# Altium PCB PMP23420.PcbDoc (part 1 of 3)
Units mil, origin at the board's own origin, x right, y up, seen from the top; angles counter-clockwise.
Board outline 5200 x 3400 mil, 6 copper layers (Top Layer, Midlayer 1, Midlayer 2, Midlayer 3, Midlayer 4, Bottom Layer), stack 61.536 mil thick; 227 components, 56 nets, 480 pads, 964 vias.
Unrouted connection lines stored in the file: 22.
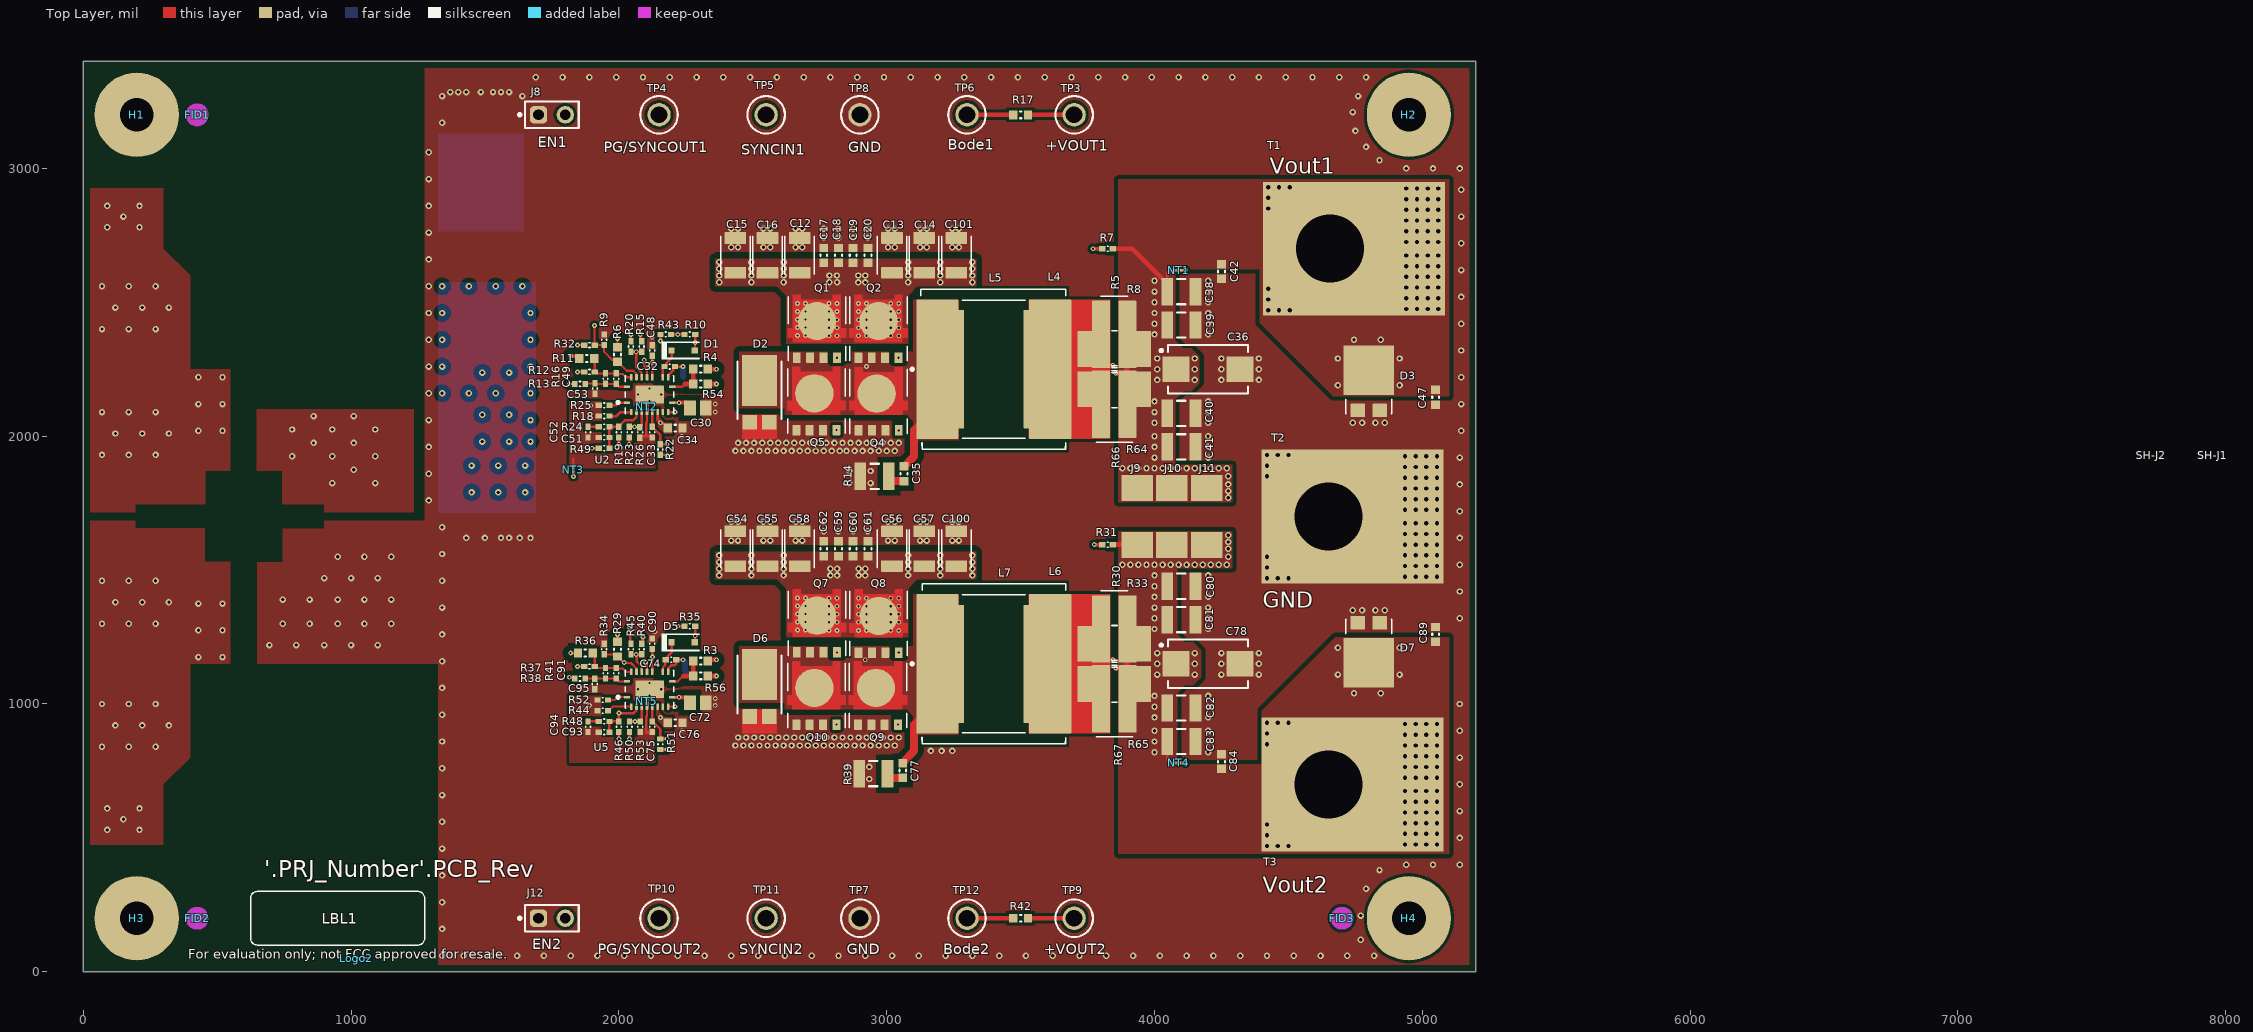
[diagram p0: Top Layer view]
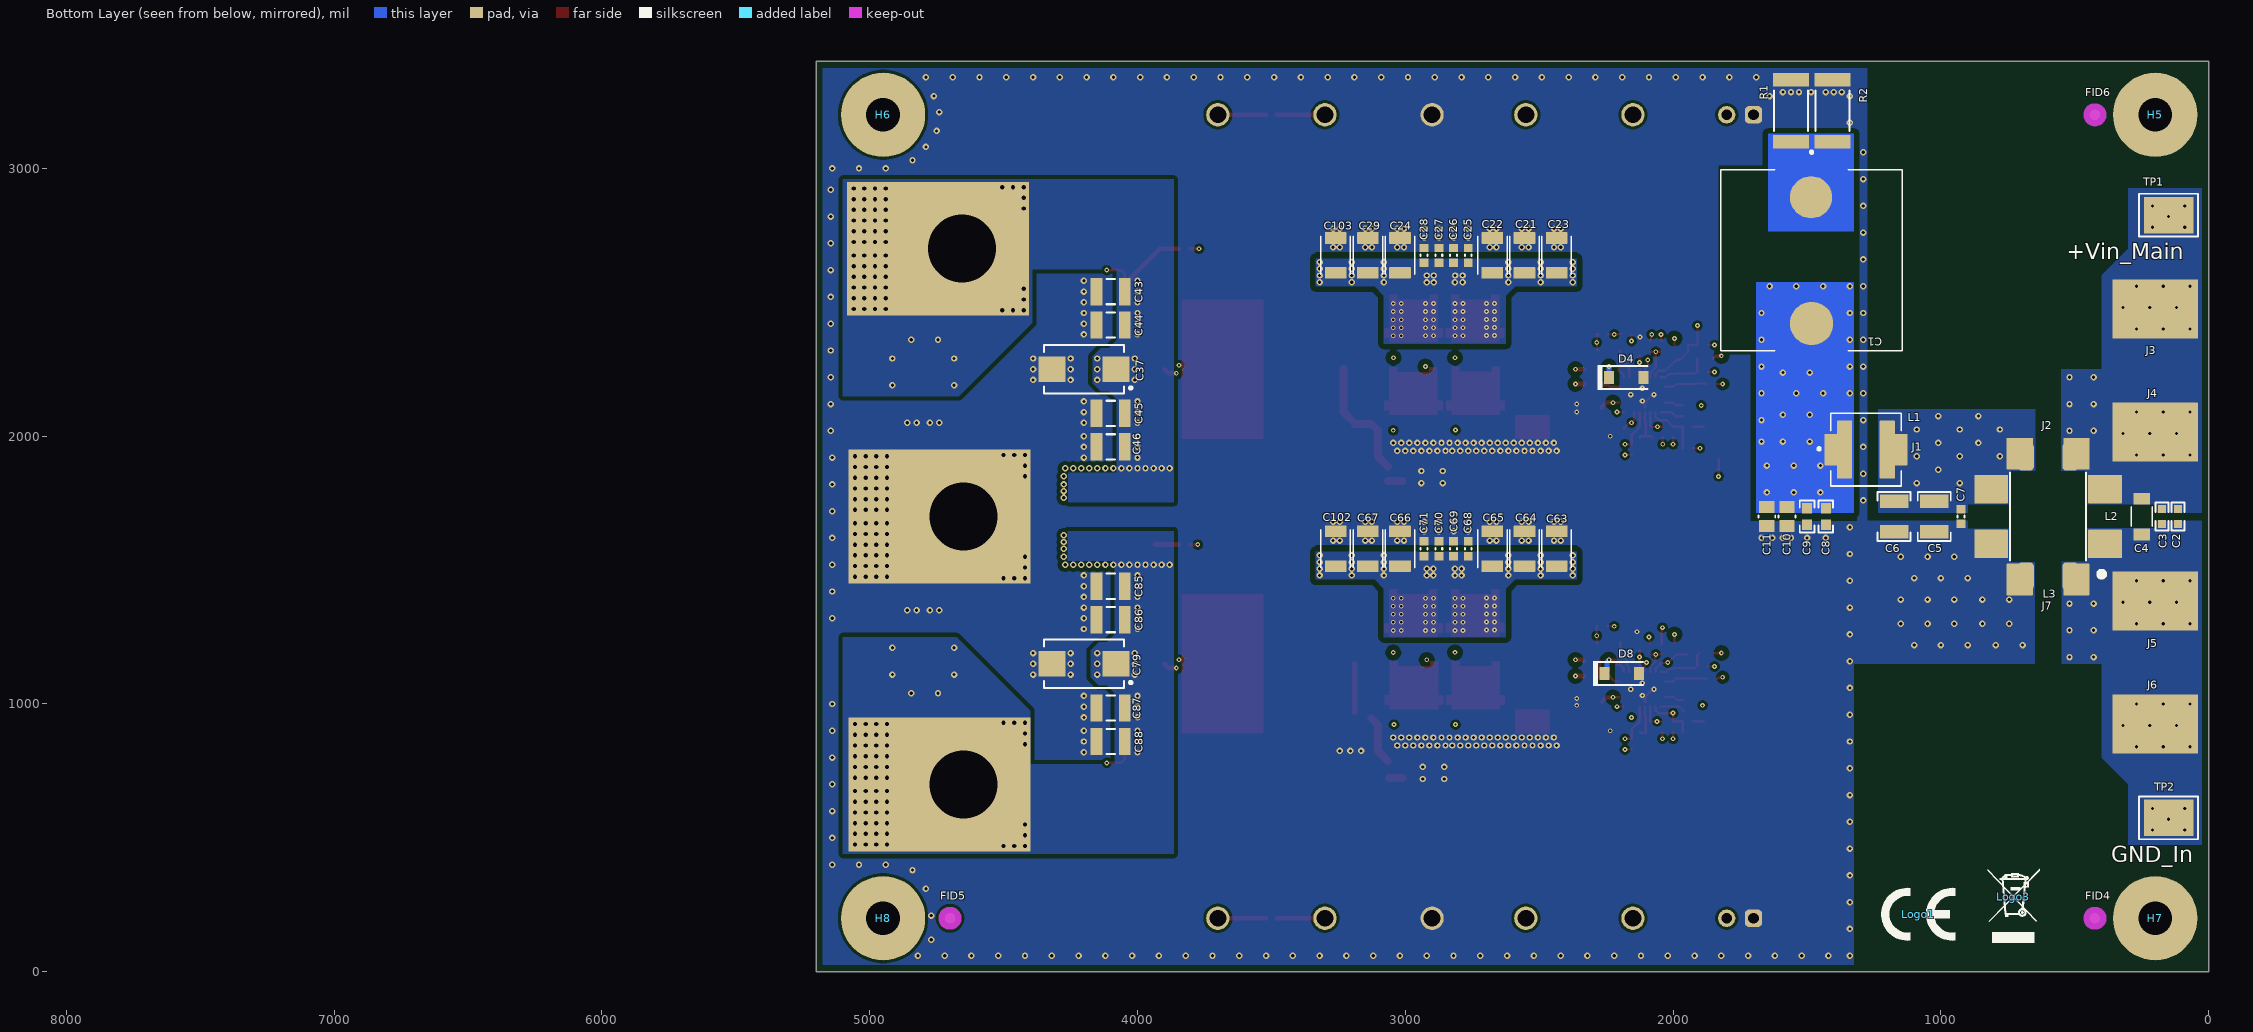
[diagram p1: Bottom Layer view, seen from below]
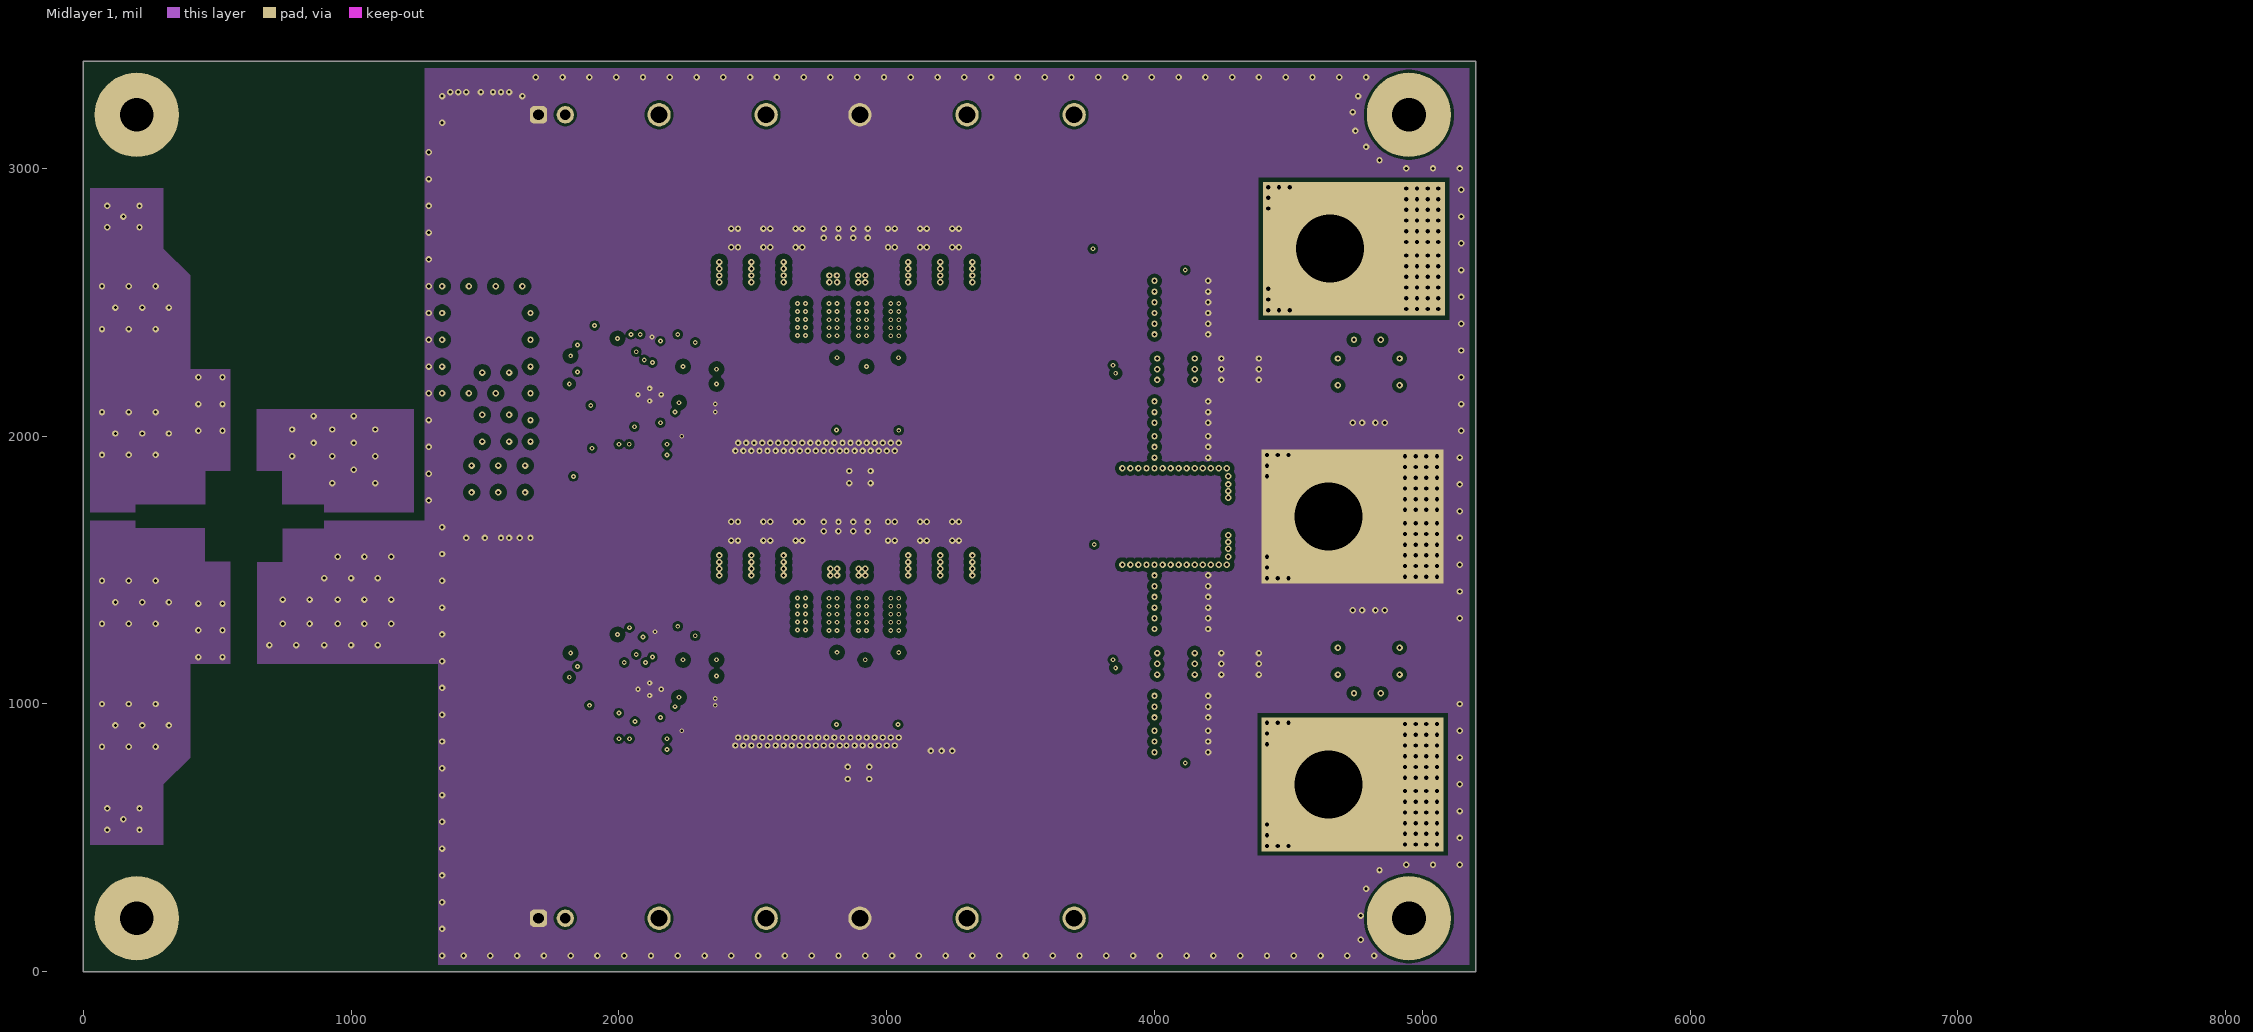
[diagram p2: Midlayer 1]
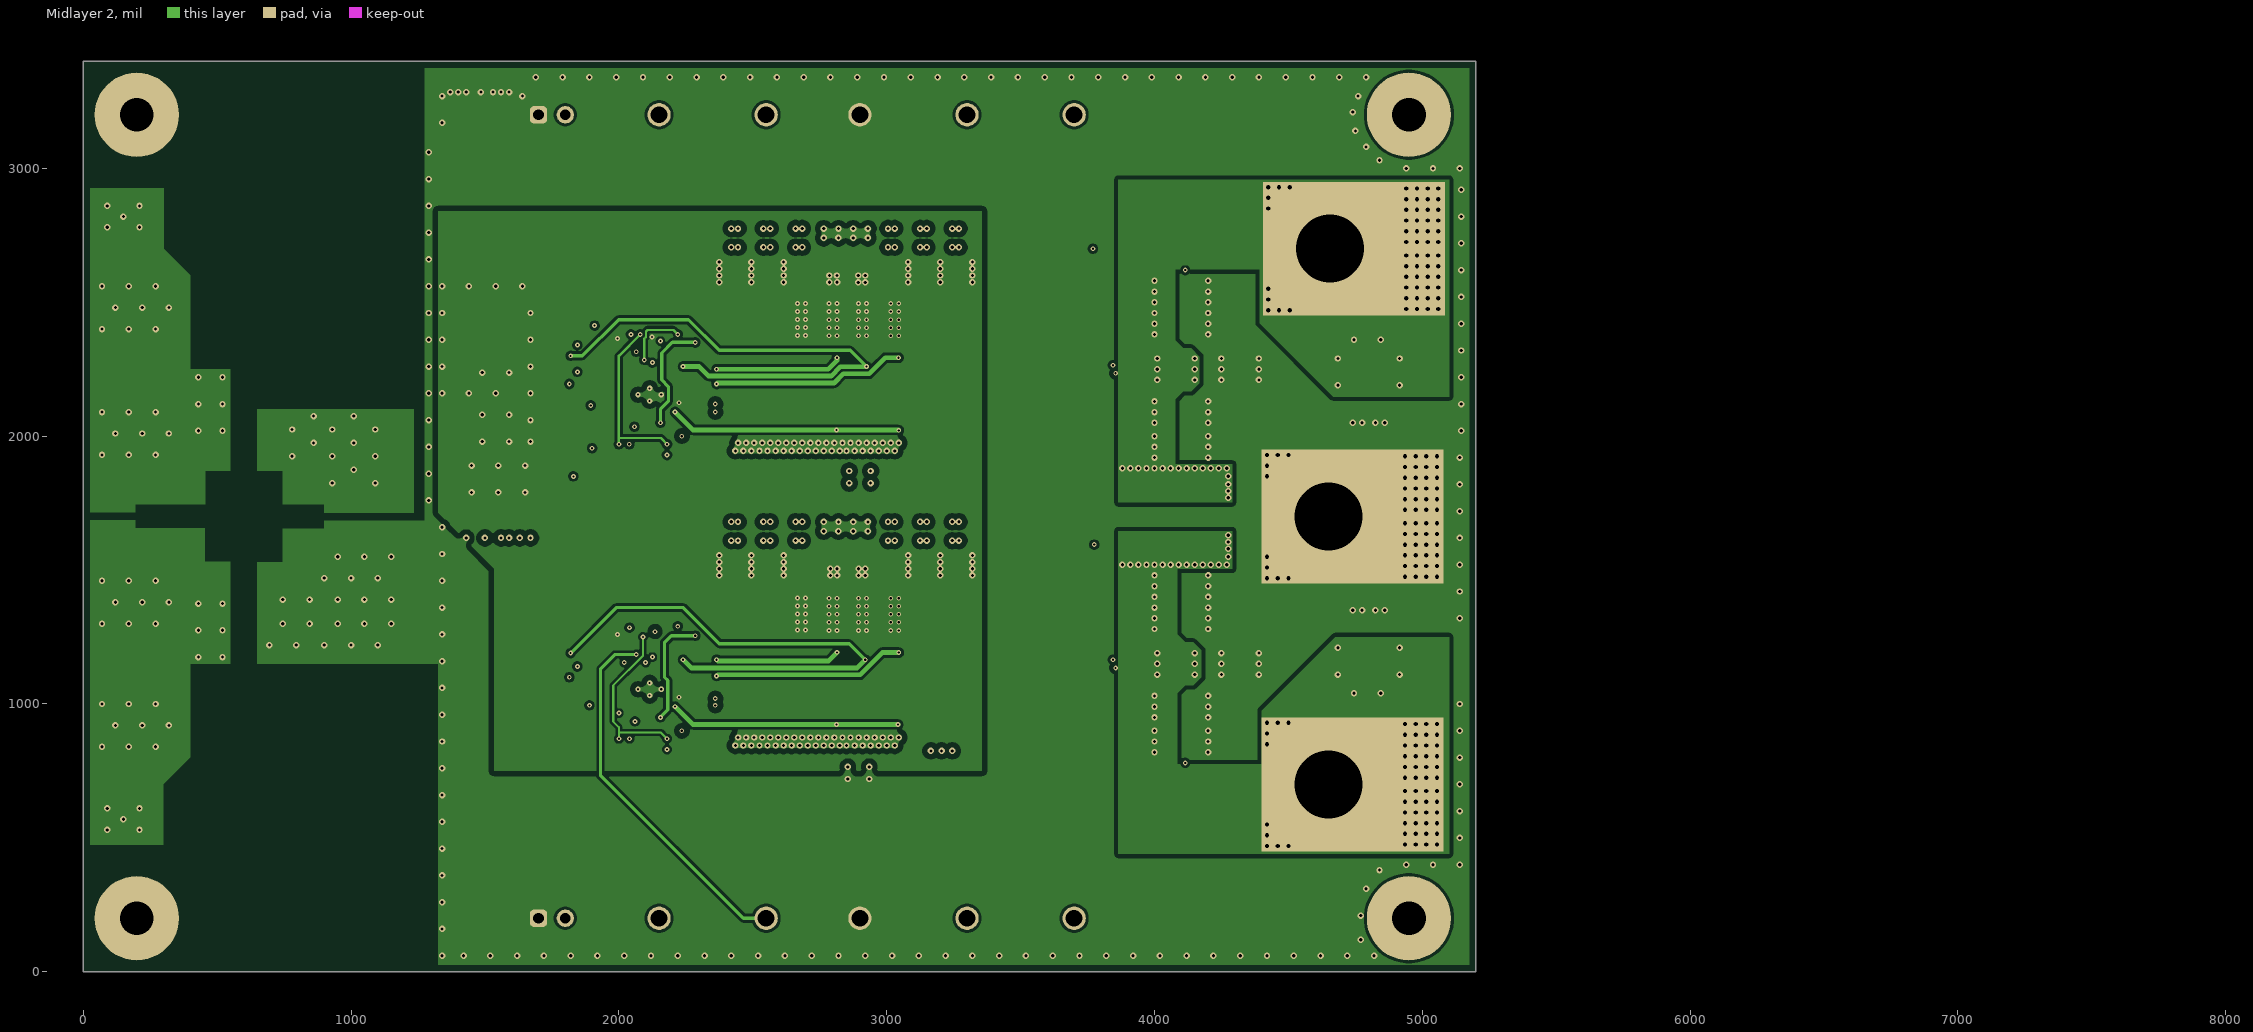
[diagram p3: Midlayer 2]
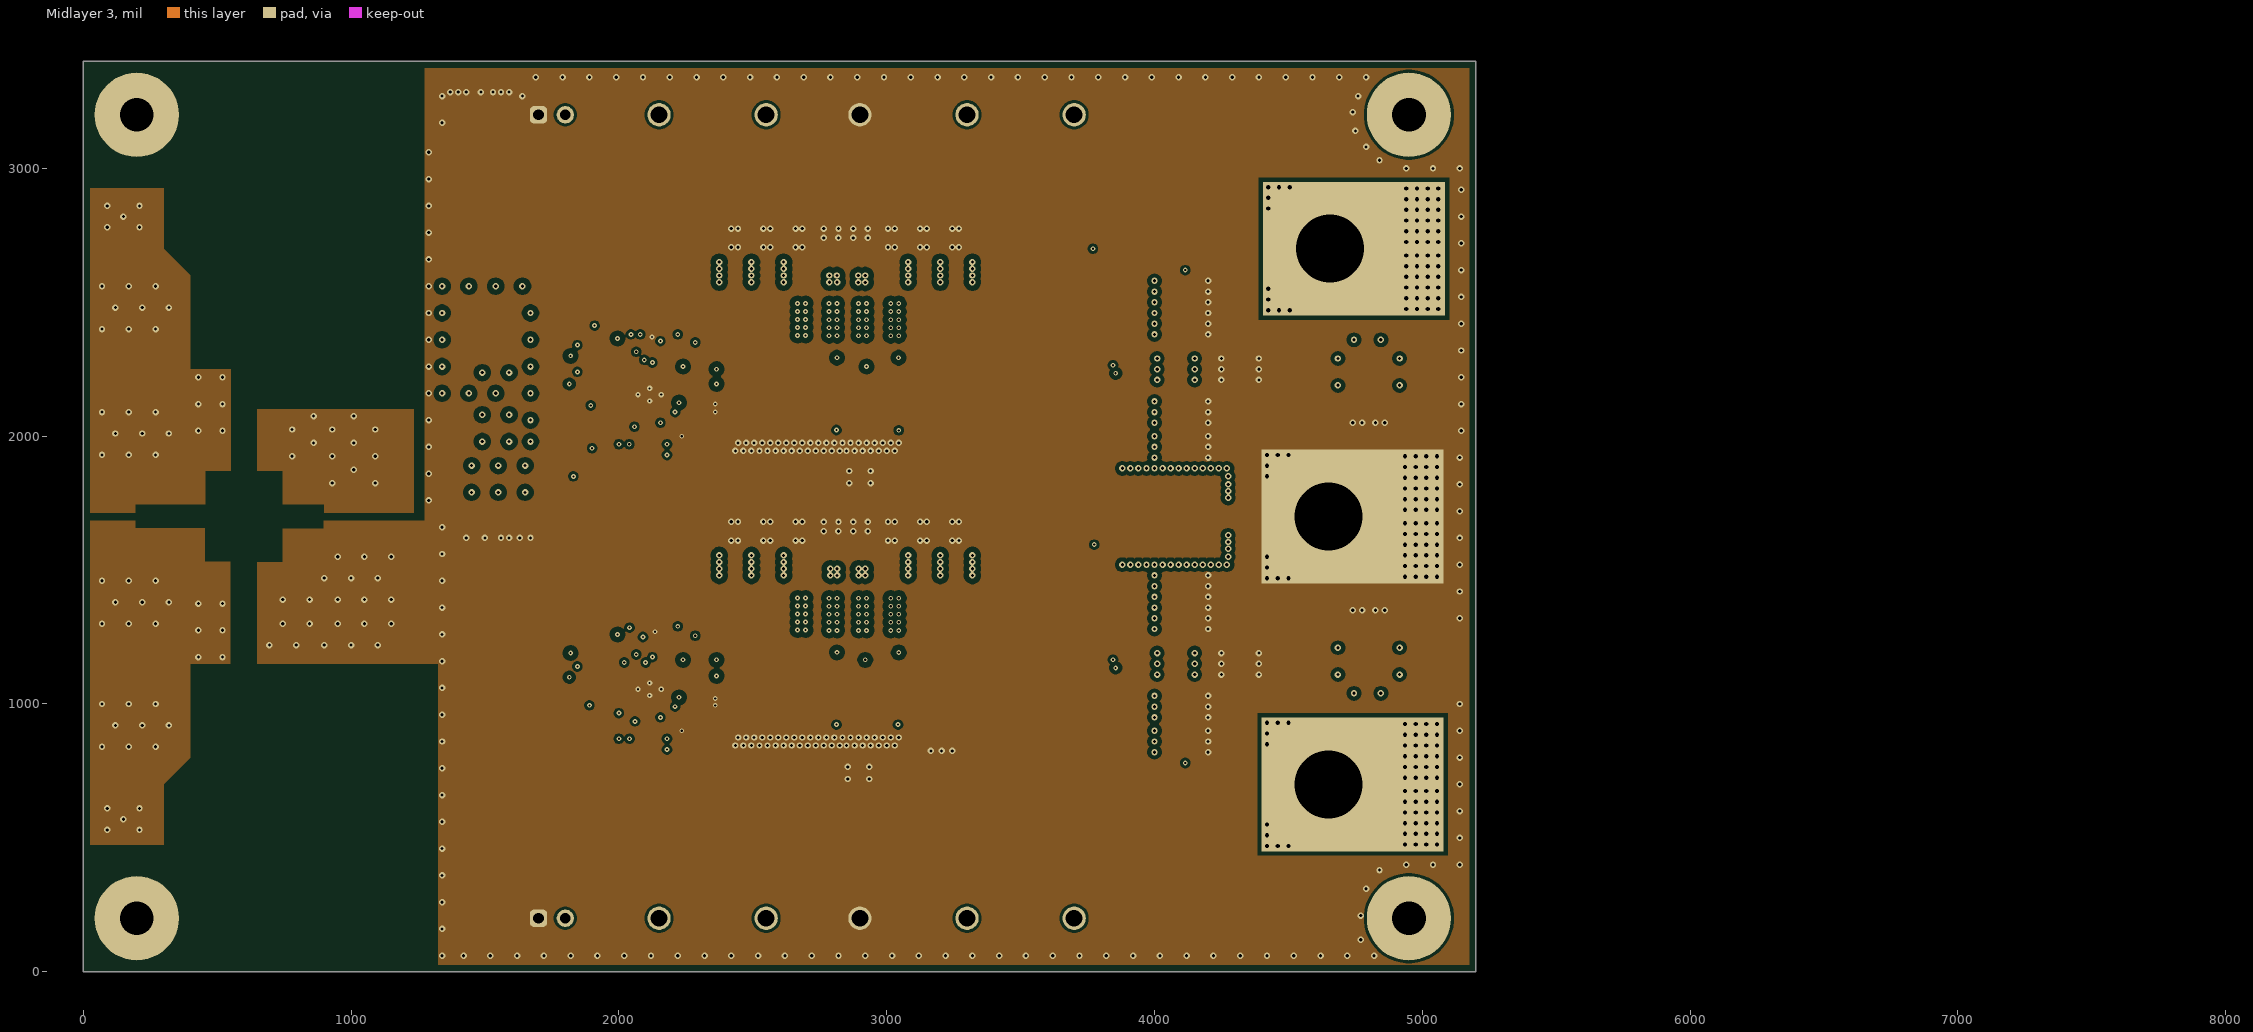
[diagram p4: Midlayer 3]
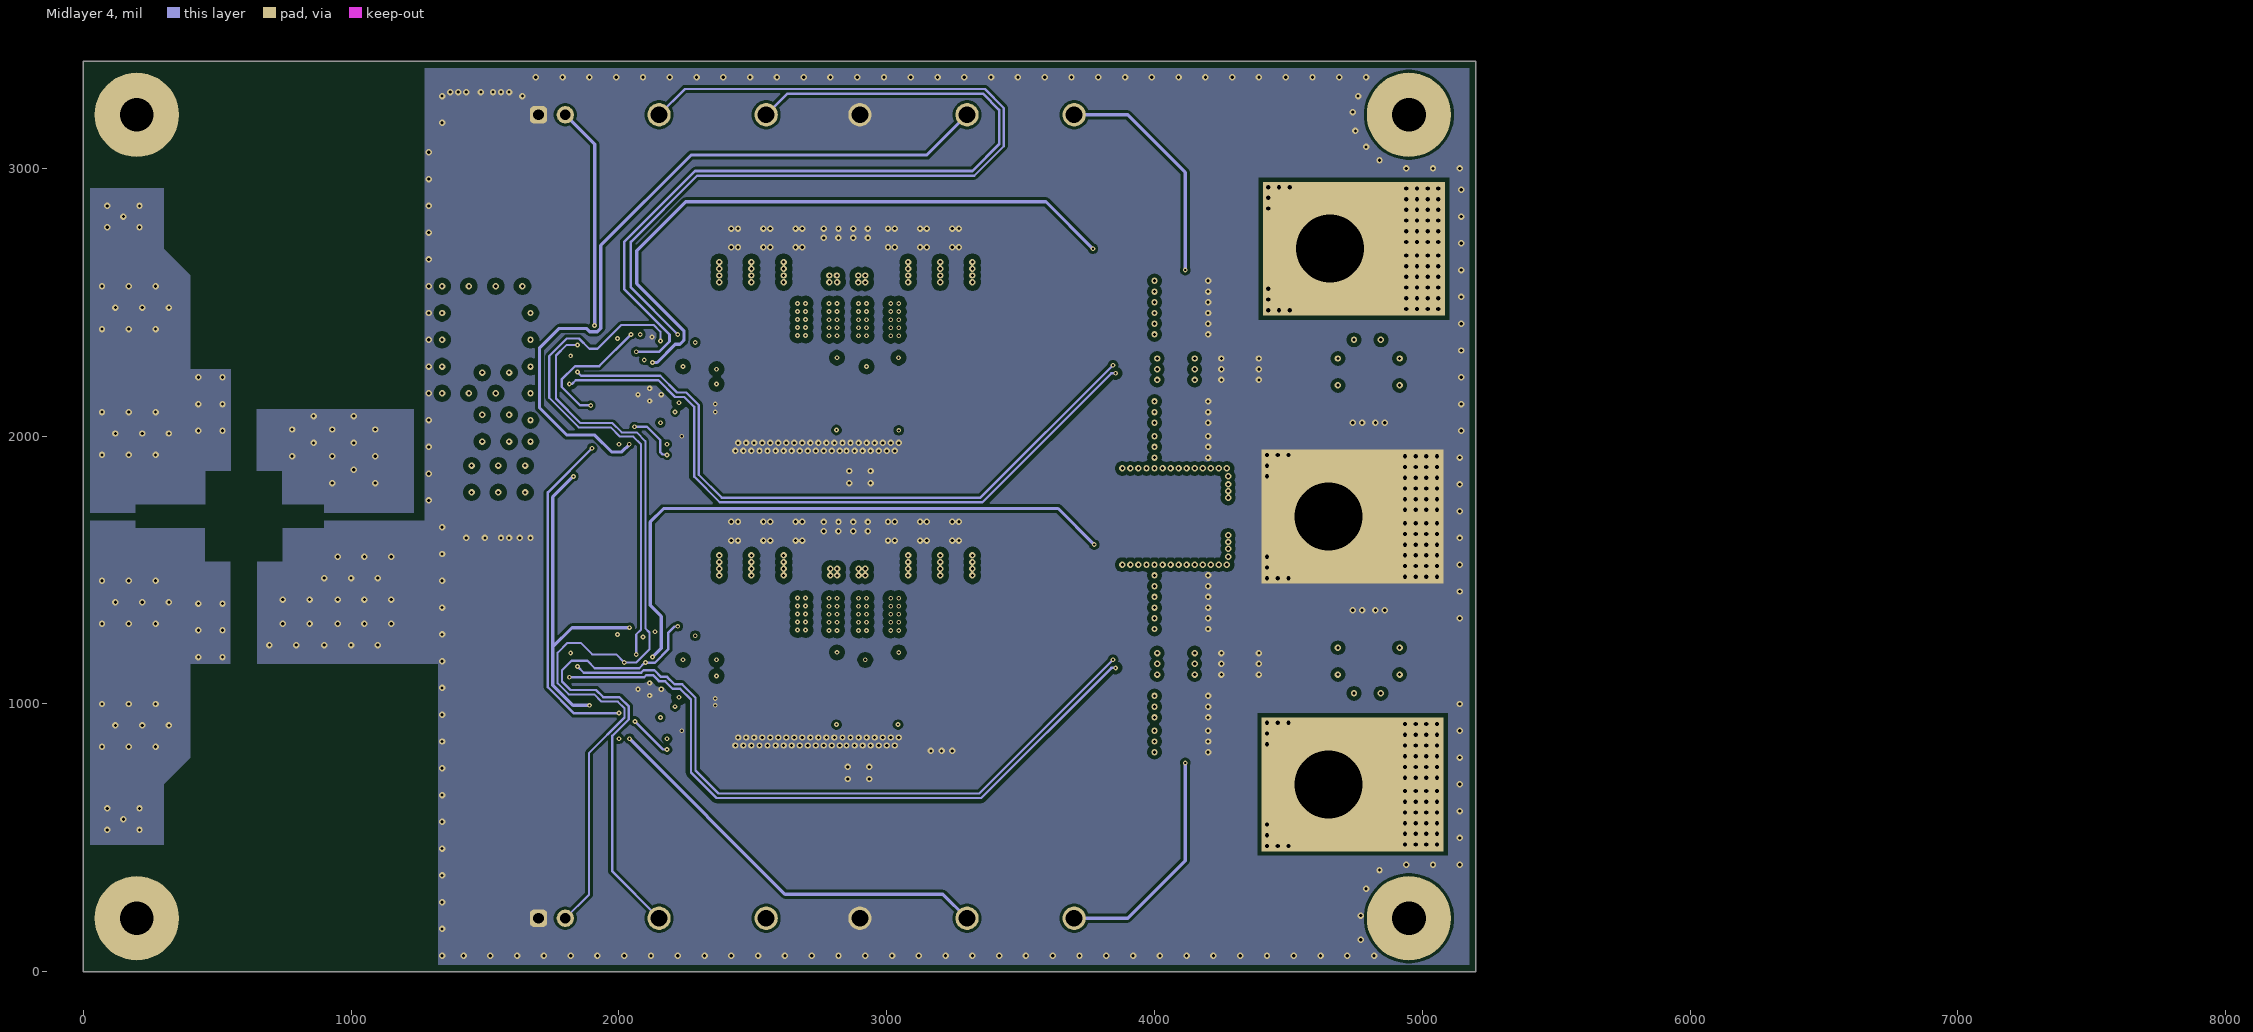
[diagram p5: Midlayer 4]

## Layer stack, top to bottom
Top Solder: solder mask 0.4, Solder Resist, Dk 3.5
Top Layer: signal copper 2.756
Dielectric 1: prepreg 9, PP-023, Dk 4.5
Midlayer 1: signal copper 2.7559
Dielectric 2: prepreg 9, PP-023, Dk 4.5
Midlayer 2: signal copper 2.7559
Dielectric3: core 9, Core-034, Dk 4.6
Midlayer 3: signal copper 2.7559
Dielectric 4: prepreg 9, PP-023, Dk 4.5
Midlayer 4: signal copper 2.7559
Dielectric 5: prepreg 9, PP-023, Dk 4.5
Bottom Layer: signal copper 2.756
Bottom Solder: solder mask 0.4, Solder Resist, Dk 3.5

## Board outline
0,0 5200,0 5200,3400 0,3400

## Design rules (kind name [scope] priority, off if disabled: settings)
AcuteAngle [All] p1: minimum=4.50000000000000E+0001 checktracksonly=FALSE
AssemblyTestPointUsage [All] p1: valid=2
BoardOutlineClearance BoardOutlineClearance_MountingHoles [OnCopper and InComponentClass('Mounting Holes')] p1: gap=39.37 ignorepadtopadclearanceinfootprint=FALSE
BoardOutlineClearance BoardOutlineClearance_Poly [OnCopper and IsPoly] p2: gap=25 ignorepadtopadclearanceinfootprint=FALSE
BoardOutlineClearance [OnCopper and Not InComponentClass('Logo') and not InComponentClass('FiducialMark') and not InRegion(1000,500,4000,800) and not InPoly] p3: gap=40 ignorepadtopadclearanceinfootprint=FALSE
Clearance Clearance_HV [InNetClass('HV') vs InNet('GND')] p1: gap=20 ignorepadtopadclearanceinfootprint=TRUE
Clearance Clearance_VOUT [(InNet('VOUT1') OR InNet('VOUT2')) vs InNet('GND')] p2: gap=15 ignorepadtopadclearanceinfootprint=TRUE
Clearance Clearance_Keepouts [((IsTrack Or IsArc) And Not InPoly) And IsFree and IsKeepOut vs ((IsTrack Or IsArc) And Not InPoly) And IsFree and IsKeepOut] p3: gap=0 ignorepadtopadclearanceinfootprint=FALSE
Clearance Clearance_Poly [InPolygon] p4: gap=10 ignorepadtopadclearanceinfootprint=TRUE
Clearance Clearance_FiducialMark [IsKeepOut and InComponentClass('FiducialMark') vs IsPad and InComponentClass('FiducialMark')] p5: gap=0 ignorepadtopadclearanceinfootprint=FALSE
Clearance [All] p6: gap=7.87 ignorepadtopadclearanceinfootprint=TRUE
ComponentClearance ComponentClearance_L3,J2 [InComponent('L3') vs InComponent('J2')] p1: gap=-1 collisioncheckmode=3 verticalgap=100000 showdistances=FALSE
ComponentClearance "ComponentClearance_L1, J1" [InComponent('L1') vs InComponent('J1')] p2: gap=-1 collisioncheckmode=3 verticalgap=100000 showdistances=FALSE
ComponentClearance "ComponentClearance_L2, J2" [InComponent('L2') vs InComponent('J2')] p3: gap=-1 collisioncheckmode=3 verticalgap=100000 showdistances=FALSE
ComponentClearance "ComponentClearance_L3, J7" [InComponent('L3') vs InComponent('J7')] p4: gap=-1 collisioncheckmode=3 verticalgap=100000 showdistances=FALSE
ComponentClearance "ComponentClearance_L2, J7" [InComponent('L2') vs InComponent('J7')] p5: gap=-1 collisioncheckmode=3 verticalgap=100000 showdistances=FALSE
ComponentClearance "ComponentClearance_L2, J4" [InComponent('L2') vs InComponent('J4')] p6: gap=-1 collisioncheckmode=3 verticalgap=100000 showdistances=FALSE
ComponentClearance ComponentClearance_L2,L3 [InComponent('L2') vs InComponent('L3')] p7: gap=-1 collisioncheckmode=3 verticalgap=100000 showdistances=FALSE
ComponentClearance "ComponentClearance_NT5, U5" [InComponent('NT5') vs InComponent('U5')] p8: gap=-1 collisioncheckmode=3 verticalgap=100000 showdistances=FALSE
ComponentClearance "ComponentClearance_NT2, U2" [InComponent('NT2') vs InComponent('U2')] p9: gap=-1 collisioncheckmode=3 verticalgap=100000 showdistances=FALSE
ComponentClearance ComponentClearance_R5,R8 [InComponent('R5') vs InComponent('R8')] p10: gap=-1 collisioncheckmode=3 verticalgap=100000 showdistances=FALSE
ComponentClearance ComponentClearance_R5,R66 [InComponent('R5') vs InComponent('R66')] p11: gap=-1 collisioncheckmode=3 verticalgap=100000 showdistances=FALSE
ComponentClearance "ComponentClearance_R8, R66" [InComponent('R8') vs InComponent('R66')] p12: gap=-1 collisioncheckmode=3 verticalgap=100000 showdistances=FALSE
ComponentClearance ComponentClearance_R5,R64 [InComponent('R5') vs InComponent('R64')] p13: gap=-1 collisioncheckmode=3 verticalgap=100000 showdistances=FALSE
ComponentClearance "ComponentClearance_R64, R66" [InComponent('R64') vs InComponent('R66')] p14: gap=-1 collisioncheckmode=3 verticalgap=100000 showdistances=FALSE
ComponentClearance "ComponentClearance_L4, L5" [(InComponent('L4') OR InComponent('L5'))] p15: gap=-1 collisioncheckmode=3 verticalgap=100000 showdistances=FALSE
ComponentClearance "ComponentClearance_L6, L7" [(InComponent('L6') OR InComponent('L7'))] p16: gap=-1 collisioncheckmode=3 verticalgap=100000 showdistances=FALSE
ComponentClearance ComponentClearance_R30,R33 [InComponent('R30') vs InComponent('R33')] p17: gap=-1 collisioncheckmode=3 verticalgap=100000 showdistances=FALSE
ComponentClearance "ComponentClearance_R33, R67" [InComponent('R33') vs InComponent('R67')] p18: gap=-1 collisioncheckmode=3 verticalgap=100000 showdistances=FALSE
ComponentClearance ComponentClearance_R30,R65 [InComponent('R30') vs InComponent('R65')] p19: gap=-1 collisioncheckmode=3 verticalgap=100000 showdistances=FALSE
ComponentClearance ComponentClearance_R30,R67 [InComponent('R30') vs InComponent('R67')] p20: gap=-1 collisioncheckmode=3 verticalgap=100000 showdistances=FALSE
ComponentClearance "ComponentClearance_R65, R67" [InComponent('R65') vs InComponent('R67')] p21: gap=-1 collisioncheckmode=3 verticalgap=100000 showdistances=FALSE
ComponentClearance ComponentClearance_MountingHoles_FiducialMarks [InComponentClass('Mounting Holes') vs InComponentClass('FiducialMark')] p22: gap=50 collisioncheckmode=3 verticalgap=10 showdistances=FALSE
ComponentClearance ComponentClearance_Shunt [InComponentClass('Header') vs InComponentClass('Shunt')] p23: gap=0 collisioncheckmode=3 verticalgap=0 showdistances=FALSE
ComponentClearance ComponentClearance_Logo [InComponentClass('Logo')] p24: gap=30 collisioncheckmode=3 verticalgap=10 showdistances=FALSE
ComponentClearance ComponentClearance_ScrewToNut [(HasFootprint('NY PMS 440 0025 PH')) vs (HasFootprint('Keystone_1902C'))] p25: gap=5 collisioncheckmode=3 verticalgap=10 showdistances=FALSE
ComponentClearance ComponentClearance_MountingHoles [InComponentClass('Mounting Holes')] p26: gap=100 collisioncheckmode=3 verticalgap=100000 showdistances=FALSE
ComponentClearance ComponentClearance_SmallPassives [HasFootprint('0201*') or HasFootprint('0402*') or HasFootprint('0508') or HasFootprint('0603*') or HasFootprint('0612') or HasFootprint('0805*') or HasFootprint('0815*') or HasFootprint('0830*') or HasFootprint('1206*') or HasFootprint('1210*') or HasFootprint('1808*') or HasFootprint('1812*') or HasFootprint('1825*') or HasFootprint('2010*') or HasFootprint('2220*') or HasFootprint('2225*') or HasFootprint('2512*') or HasFootprint('2728*') or HasFootprint('3518*') vs HasFootprint('0201*') or HasFootprint('0402*') or HasFootprint('0508') or HasFootprint('0603*') or HasFootprint('0612') or HasFootprint('0805*') or HasFootprint('0815*') or HasFootprint('0830*') or HasFootprint('1206*') or HasFootprint('1210*') or HasFootprint('1808*') or HasFootprint('1812*') or HasFootprint('1825*') or HasFootprint('2010*') or HasFootprint('2220*') or HasFootprint('2225*') or HasFootprint('2512*') or HasFootprint('2728*') or HasFootprint('3518*')] p27: gap=14.96 collisioncheckmode=3 verticalgap=10 showdistances=FALSE
ComponentClearance ComponentClearance_THtoSMT [IsThruComponent vs IsSMTComponent] p28: gap=30 collisioncheckmode=3 verticalgap=30 showdistances=FALSE
ComponentClearance ComponentClearance_THtoTH [IsThruComponent vs IsThruComponent] p29: gap=20 collisioncheckmode=3 verticalgap=30 showdistances=FALSE
ComponentClearance [All] p30: gap=20 collisioncheckmode=3 verticalgap=10 showdistances=FALSE
DiffPairsRouting [All] p1: maxlimit=100 minlimit=10 mostfreqgap=10 toplayer_minwidth=15 toplayer_maxwidth=15 toplayer_prefwidth=15 midlayer1_minwidth=15 midlayer1_maxwidth=15 midlayer1_prefwidth=15 midlayer2_minwidth=15 midlayer2_maxwidth=15 midlayer2_prefwidth=15 midlayer3_minwidth=15 midlayer3_maxwidth=15 midlayer3_prefwidth=15 midlayer4_minwidth=15 midlayer4_maxwidth=15 midlayer4_prefwidth=15 bottomlayer_minwidth=15 bottomlayer_maxwidth=15 bottomlayer_prefwidth=15 maxuncoupledlength=1000
FabricationTestPointUsage TestPointUsage [All] p1: valid=2 allowmultiple=FALSE
FabricationTestpoint Testpoint [All] p1: side=3 testpointundercomponent=TRUE minsize=40 maxsize=100 preferedsize=60 minholesize=0 maxholesize=40 preferedholesize=32 testpointgrid=1 allowsidetop=TRUE allowsidebottom=TRUE usegrid=TRUE gridtolerance=0.01
FanoutControl Fanout_LCC [IsLCC] p1: bgadir=Out bgaviamode=Centered fanoutstyle=Auto fanoutdirection=Alternating viagrid=1 // Fanout_LCC (Default Rule)
FanoutControl Fanout_BGA [IsBGA] p2: bgadir=Out bgaviamode=Centered fanoutstyle=Auto fanoutdirection=Alternating viagrid=1 // Fanout_BGA (Default Rule)
FanoutControl Fanout_Default [All] p4: bgadir=Out bgaviamode=Centered fanoutstyle=Auto fanoutdirection=Alternating viagrid=1 // Fanout_Default (Default Rule)
FanoutControl Fanout_Small [(CompPinCount < 5)] p5: bgadir=Out bgaviamode=Centered fanoutstyle=Auto fanoutdirection=OutThenIn viagrid=1 // Fanout_Small (Default Rule)
HoleSize [All] p1: absolutevalues=TRUE maxlimit=255 minlimit=7.87 maxpercent=80.000 minpercent=20.000
MinimumAnnularRing MinimumAnnularRing_ThermalPadVias [IsVia and InAnyComponent] p1: minimumring=5.91
MinimumAnnularRing [All] p2: minimumring=5
MinimumSolderMaskSliver MinimumSolderMaskSliver_Logo [InComponentClass('Logo') vs InComponentClass('Logo')] p1: minsoldermaskwidth=0.7
MinimumSolderMaskSliver [All] p2: minsoldermaskwidth=3.94
PlaneConnect [All] p1: planeconnectstyle=Direct reliefexpansion=10 reliefentries=4 reliefconductorwidth=10 reliefairgap=10
PolygonConnect [All] p1: connectstyle=Direct reliefconductorwidth=10 reliefentries=4 polygonreliefangle="90 Angle" airgapwidth=10
RoutingVias ThermalPadVias [IsVia and InAnyComponent] p1: holewidth=7.87 width=19.68 viastyle="Through Hole" minholewidth=7.87 minwidth=18 maxholewidth=40 maxwidth=50
RoutingVias [All] p2: holewidth=16 width=34 viastyle="Through Hole" minholewidth=7.87 minwidth=18 maxholewidth=40 maxwidth=65
SilkToBoardRegionClearance [Not ((IsComment or IsDesignator) And (Hide <> 'False')) and not InRegion(1000,500,4000,800)] p1:
SilkToSilkClearance SilkToSilkClearance_Pb-FreeLogo [(HasFootprint('Pb-Free_Overlay_Medium') OR HasFootprint('Pb-Free_Overlay_Small')) vs (HasFootprint('Pb-Free_Overlay_Medium') OR HasFootprint('Pb-Free_Overlay_Small'))] p1: silktosilkclearance=0
SilkToSilkClearance [All] p2: silktosilkclearance=1
SilkToSolderMaskClearance SilkToComponentPadClearance [(IsPad or IsFill or IsRegion) and InAnycomponent] p1: minsilkscreentomaskgap=2 clearancetoexposedcopper=TRUE
SilkToSolderMaskClearance "Silk to Solder Mask Opening" [All] p2: minsilkscreentomaskgap=2 clearancetoexposedcopper=FALSE
SolderMaskExpansion [All] p1: expansion=1.97 istentingtop=FALSE
UnRoutedNet [All] p1: checkbadconnections=TRUE
Width [All] p1: maxlimit=100 minlimit=6 preferedwidth=10 checkconnectedcopper=TRUE
14 further rules are at their usual default settings.

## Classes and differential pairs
net class HV: +Filter +Vin_Main HO1 HO2 NetC1_1 NetC35_2 NetC77_2 NetQ1_4 NetQ2_4 NetQ7_4 NetQ8_4 SW1 SW2 Vbst1 Vbst2 VIN
component class Shunt: SH-J1 SH-J2
component class PMP23420_Schematic: C1 C2 C3 C4 C5 C6 C7 C8 C9 C10 C11 C12 C13 C14 C15 C16 C17 C18 C19 C20 C21 C22 C23 C24 C25 C26 C27 C28 C29 C30 C32 C33 C34 C35 C36 C37 C38 C39 C40 C41 C42 C43 C44 C45 C46 C47 C48 C49 C51 C52 C53 C54 C55 C56 C57 C58 C59 C60 C61 C62 C63 C64 C65 C66 C67 C68 C69 C70 C71 C72 C74 C75 C76 C77 C78 C79 C80 C81 C82 C83 C84 C85 C86 C87 C88 C89 C90 C91 C93 C94 C95 C100 C101 C102 C103 D1 D2 D3 D4 D5 D6 D7 D8 J1 J2 J3 J4 J5 J6 J7 J8 J9 J10 J11 J12 L1 L2 L3 L4 L5 L6 L7 NT1 NT2 NT3 NT4 NT5 Q1 Q2 Q4 Q5 Q7 Q8 Q9 Q10 R1 R2 R3 R4 R5 R6 R7 R8 R9 R10 R11 R12 R13 R14 R15 R16 R17 R18 R19 R20 R22 R23 R24 R25 R26 R29 R30 R31 R32 R33 R34 R35 R36 R37 R38 R39 R40 R41 R42 R43 R44 R45 R46 R48 R49 R50 R51 R52 R53 R54 R56 R64 R65 R66 R67 SH-J1 SH-J2 T1 T2 T3 TP1 TP2 TP3 TP4 TP5 TP6 TP7 TP8 TP9 TP10 TP11 TP12 U2 U5
component class Header: J8 J12
component class Label: LBL1
component class FiducialMark: FID1 FID2 FID3 FID4 FID5 FID6
component class PMP23420_Hardware: FID1 FID2 FID3 FID4 FID5 FID6 H1 H2 H3 H4 H5 H6 H7 H8 LBL1 Logo1 Logo2 Logo3
component class "Mounting Holes": H1 H2 H3 H4

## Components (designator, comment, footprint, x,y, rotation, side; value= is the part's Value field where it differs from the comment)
C1 "EEE-TP1K391V" FP-EEE-TP1K391V_SMT_CAP_17MM0_17MM0-MFG 1483,2657 r270 bottom value=390µF
C2 "GCM188R72A103KA37J" 0603_HV 115,1700 r270 bottom value=0.01uF
C3 "GCM188R72A103KA37J" 0603_HV 175,1700 r270 bottom value=0.01uF
C4 "CGA5L3X7S2A225K160AB" 1206_180 250,1700 r270 bottom value=2.2uF
C5 "C3225X7S2A475K200AB" 1210_220 1025,1700 r90 bottom value=4.7uF
C6 "CGA6M3X7S2A475K200AB" 1210_220 1175,1700 r90 bottom value=4.7uF
C7 "GCM188R72A103KA37J" 0603L 925,1700 r270 bottom value=0.01uF
C8 "GCM188R72A103KA37J" 0603 1430,1700 r270 bottom value=0.01uF
C9 "GCM188R72A103KA37J" 0603 1500,1700 r270 bottom value=0.01uF
C10 "08051C105K4Z2A" 0805_150 1575,1700 r270 bottom value=1uF
C11 "08051C105K4Z2A" 0805_150 1650,1700 r270 bottom value=1uF
C12 "GCJ32DC72A475KE01L" FP-GCJ32DC72A475KE01L_1210-MFG 2675,2675 r270 top value=4.7µF
C13 "GCJ32DC72A475KE01L" FP-GCJ32DC72A475KE01L_1210-MFG 3020,2675 r270 top value=4.7µF
C14 "GCJ32DC72A475KE01L" FP-GCJ32DC72A475KE01L_1210-MFG 3140,2675 r270 top value=4.7µF
C15 "GCJ32DC72A475KE01L" FP-GCJ32DC72A475KE01L_1210-MFG 2435,2675 r270 top value=4.7µF
C16 "GCJ32DC72A475KE01L" FP-GCJ32DC72A475KE01L_1210-MFG 2555,2675 r270 top value=4.7µF
C17 "GCJ188R72A104KA01D" 0603L 2765,2675 r90 top value=0.1uF
C18 "GCJ188R72A104KA01D" 0603L 2820,2675 r90 top value=0.1uF
C19 "GCJ188R72A104KA01D" 0603L 2875,2675 r90 top value=0.1uF
C20 "GCJ188R72A104KA01D" 0603L 2930,2675 r90 top value=0.1uF
C21 "DNP" FP-GCJ32DC72A475KE01L_1210-MFG 2555,2675 r270 bottom value=4.7µF
C22 "DNP" FP-GCJ32DC72A475KE01L_1210-MFG 2675,2675 r270 bottom value=4.7µF
C23 "DNP" FP-GCJ32DC72A475KE01L_1210-MFG 2435,2675 r270 bottom value=4.7µF
C24 "DNP" FP-GCJ32DC72A475KE01L_1210-MFG 3020,2675 r270 bottom value=4.7µF
C25 "DNP" 0603L 2765,2675 r90 bottom value=0.1uF
C26 "DNP" 0603L 2820,2675 r90 bottom value=0.1uF
C27 "DNP" 0603L 2875,2675 r90 bottom value=0.1uF
C28 "DNP" 0603L 2930,2675 r90 bottom value=0.1uF
C29 "DNP" FP-GCJ32DC72A475KE01L_1210-MFG 3140,2675 r270 bottom value=4.7µF
C30 "KAF21KR72A474KU" 0805L 2295,2105 r0 top value=0.47uF
C32 "CGA2B1X7R1V224K050BC" 0402L 2190,2260 r0 top value=0.22uF
C33 "C0402C104K8RACAUTO" 0402L 2125,2015 r90 top value=0.1uF
C34 "GRM188Z71A475ME15D" 0603L 2210,2030 r0 top value=4.7uF
C35 "DNP" 0603L 3065,1860 r270 top value=330pF
C36 "DNP" 7343-31 4200,2250 r0 top value=220uF
C37 "DNP" 7343-31 4200,2250 r0 bottom value=220uF
C38 "GRT32EC70J107ME13K" 1210L 4100,2540 r0 top value=100uF
C39 "GRT32EC70J107ME13K" 1210L 4100,2415 r0 top value=100uF
C40 "GRT32EC70J107ME13K" 1210L 4100,2085 r0 top value=100uF
C41 "GRT32EC70J107ME13K" 1210L 4100,1960 r0 top value=100uF
C42 "C0603C104K5RACTU" 0603L 4250,2615 r270 top value=0.1uF
C43 "GRT32EC70J107ME13K" 1210L 4100,2540 r0 bottom value=100uF
C44 "GRT32EC70J107ME13K" 1210L 4100,2415 r0 bottom value=100uF
C45 "GRT32EC70J107ME13K" 1210L 4100,2085 r0 bottom value=100uF
C46 "GRT32EC70J107ME13K" 1210L 4100,1960 r0 bottom value=100uF
C47 "Capacitor" 0603L 5050,2145 r270 top value=0.1uF
C48 "C0402C104K8RACAUTO" 0402L 2125,2320 r270 top value=0.1uF
C49 "CGA2B1X7R1E333K050BC" 0402L 1990,2215 r90 top value=0.033uF
C51 "CGA2B2NP01H220J050BA" 0402L 1945,1995 r180 top value=22pF
C52 "GCM155R71E223KA55D" 0402L 1885,2015 r270 top value=0.022uF
C53 "GRM155R72A271KA01D" 0402L 1911,2178 r90 top value=270pF
C54 "GCJ32DC72A475KE01L" FP-GCJ32DC72A475KE01L_1210-MFG 2435,1580 r270 top value=4.7µF
C55 "GCJ32DC72A475KE01L" FP-GCJ32DC72A475KE01L_1210-MFG 2555,1580 r270 top value=4.7µF
C56 "GCJ32DC72A475KE01L" FP-GCJ32DC72A475KE01L_1210-MFG 3020,1580 r270 top value=4.7µF
C57 "GCJ32DC72A475KE01L" FP-GCJ32DC72A475KE01L_1210-MFG 3140,1580 r270 top value=4.7µF
C58 "GCJ32DC72A475KE01L" FP-GCJ32DC72A475KE01L_1210-MFG 2675,1580 r270 top value=4.7µF
C59 "GCJ188R72A104KA01D" 0603L 2820,1580 r90 top value=0.1uF
C60 "GCJ188R72A104KA01D" 0603L 2875,1580 r90 top value=0.1uF
C61 "GCJ188R72A104KA01D" 0603L 2930,1580 r90 top value=0.1uF
C62 "GCJ188R72A104KA01D" 0603L 2765,1580 r90 top value=0.1uF
C63 "DNP" FP-GCJ32DC72A475KE01L_1210-MFG 2435,1580 r270 bottom value=4.7µF
C64 "DNP" FP-GCJ32DC72A475KE01L_1210-MFG 2555,1580 r270 bottom value=4.7µF
C65 "DNP" FP-GCJ32DC72A475KE01L_1210-MFG 2675,1580 r270 bottom value=4.7µF
C66 "DNP" FP-GCJ32DC72A475KE01L_1210-MFG 3020,1580 r270 bottom value=4.7µF
C67 "DNP" FP-GCJ32DC72A475KE01L_1210-MFG 3140,1580 r270 bottom value=4.7µF
C68 "DNP" 0603L 2765,1580 r90 bottom value=0.1uF
C69 "DNP" 0603L 2820,1580 r90 bottom value=0.1uF
C70 "DNP" 0603L 2875,1580 r90 bottom value=0.1uF
C71 "DNP" 0603L 2930,1580 r90 bottom value=0.1uF
C72 "KAF21KR72A474KU" 0805L 2295,1005 r0 top value=0.47uF
C74 "CGA2B1X7R1V224K050BC" 0402L 2195,1165 r0 top value=0.22uF
C75 "C0402C104K8RACAUTO" 0402L 2125,915 r90 top value=0.1uF
C76 "GRM188Z71A475ME15D" 0603L 2210,930 r0 top value=4.7uF
C77 "DNP" 0603L 3060.01,751.81 r270 top value=330pF
C78 "DNP" 7343-31 4200,1150 r0 top value=220uF
C79 "DNP" 7343-31 4200,1150 r0 bottom value=220uF
C80 "GRT32EC70J107ME13K" 1210L 4100,1440 r0 top value=100uF
C81 "GRT32EC70J107ME13K" 1210L 4100,1315 r0 top value=100uF
C82 "GRT32EC70J107ME13K" 1210L 4100,985 r0 top value=100uF
C83 "GRT32EC70J107ME13K" 1210L 4100,860 r0 top value=100uF
C84 "C0603C104K5RACTU" 0603L 4250,785 r90 top value=0.1uF
C85 "GRT32EC70J107ME13K" 1210L 4100,1440 r0 bottom value=100uF
C86 "GRT32EC70J107ME13K" 1210L 4100,1315 r0 bottom value=100uF
C87 "GRT32EC70J107ME13K" 1210L 4100,985 r0 bottom value=100uF
C88 "GRT32EC70J107ME13K" 1210L 4100,860 r0 bottom value=100uF
C89 "C0603C104K5RACTU" 0603L 5050,1260 r90 top value=0.1uF
C90 "C0402C104K8RACAUTO" 0402L 2125,1225 r270 top value=0.1uF
C91 "CGA2B1X7R1E333K050BC" 0402L 1990,1115 r90 top value=0.033uF
C93 "CGA2B2NP01H220J050BA" 0402L 1945,895 r180 top value=22pF
C94 "DNP" 0402L 1885,915 r270 top value=5600pF
C95 "GRM155R72A271KA01D" 0402L 1910,1075 r90 top value=270pF
C100 "GCJ32DC72A475KE01L" FP-GCJ32DC72A475KE01L_1210-MFG 3260,1580 r270 top value=4.7µF
C101 "GCJ32DC72A475KE01L" FP-GCJ32DC72A475KE01L_1210-MFG 3260,2675 r270 top value=4.7µF
C102 "DNP" FP-GCJ32DC72A475KE01L_1210-MFG 3260,1580 r270 bottom value=4.7µF
C103 "DNP" FP-GCJ32DC72A475KE01L_1210-MFG 3260,2675 r270 bottom value=4.7µF
D1 "BAT46WJ,115" SOD-323F 2240,2320 r0 top value=100V
D2 "PDS5100HQ-13" POWERDI5 2525,2130 r90 top value=100V
D3 "SS10P4HM3_A/H" FP-SS10P4HM3_A/H_SMPC-MFG 4800,2205 r0 top value=40V
D4 "PMEG10020AELRX" SOD-123 2175,2219 r180 bottom value=100V
D5 "BAT46WJ,115" SOD-323F 2240,1230 r0 top value=100V
D6 "PDS5100HQ-13" POWERDI5 2525,1031.61 r90 top value=100V
D7 "SS10P4HM3_A/H" FP-SS10P4HM3_A/H_SMPC-MFG 4800,1195 r180 top value=40V
D8 "PMEG10020AELRX" SOD-123 2192,1114 r180 bottom value=100V
FID1 "Fiducial" Fiducial10-20 425,3200 r0 top
FID2 "Fiducial" Fiducial10-20 425,200 r0 top
FID3 "Fiducial" Fiducial10-20 4700,200 r0 top
FID4 "Fiducial" Fiducial10-20 425,200 r180 bottom
FID5 "Fiducial" Fiducial10-20 4700,200 r180 bottom
FID6 "Fiducial" Fiducial10-20 425,3200 r180 bottom
H1 "NY PMS 440 0025 PH" "NY PMS 440 0025 PH" 200,3200 r0 top locked
H2 "NY PMS 440 0025 PH" "NY PMS 440 0025 PH" 4950,3200 r0 top locked
H3 "NY PMS 440 0025 PH" "NY PMS 440 0025 PH" 200,200 r0 top locked
H4 "NY PMS 440 0025 PH" "NY PMS 440 0025 PH" 4950,200 r0 top locked
H5 "1902C" Keystone_1902C 200,3200 r180 bottom locked
H6 "1902C" Keystone_1902C 4950,3200 r180 bottom locked
H7 "1902C" Keystone_1902C 200,200 r180 bottom locked
H8 "1902C" Keystone_1902C 4950,200 r180 bottom locked
J1 "" Keystone_5102 1280,1950 r180 bottom
J2 "" Keystone_5102 600,1935 r180 bottom
J3 "+Vin_Main" Cinch_108-0902-001 15,2475 r0 bottom
J4 "+Vin_Main" Cinch_108-0902-001 15,2015 r0 bottom
J5 "GND_IN" Cinch_108-0903-001 15,1385 r0 bottom
J6 "GND_IN" Cinch_108-0903-001 15,925 r0 bottom
J7 "" Keystone_5102 600,1465 r180 bottom
J8 "EN1" TSW-102-07-G-S 1750,3200 r0 top
J9 "" Keystone_5102 3935,1700 r90 top
J10 "" Keystone_5102 4065,1700 r90 top
J11 "" Keystone_5102 4195,1700 r90 top
J12 "EN2" TSW-102-07-G-S 1750,200 r0 top
L1 "DNP" FP-XGL6060-102MEC_SMT2_6MM51_6MM71-MFG 1280,1950 r180 bottom value=1uH
L2 "DNP" TDK_ACM12V 600,1700 r0 bottom
L3 "DNP" MuRata_PLT10H 600,1700 r0 bottom value=2uH
L4 "DNP" FP-XGL1313-222MED_SMT_IND_13MM4_15MM0-MFG 3400,2250 r0 top value=2.2uH
L5 "VCUD128T-2R5MS8" FP-VCUD128T-2R5MS8_SMT_IND_13MM3_12MM8-MFG 3400,2250 r0 top value=2.5uH
L6 "DNP" FP-XGL1313-222MED_SMT_IND_13MM4_15MM0-MFG 3400,1150 r0 top value=2.2uH
L7 "VCUD128T-2R5MS8" FP-VCUD128T-2R5MS8_SMT_IND_13MM3_12MM8-MFG 3400,1150 r0 top value=2.5uH
LBL1 "THT-14-423-10" Label_650x200 950,200 r0 top
Logo1 "CE Mark" CE_Mark_5mm 1085,215 r180 bottom
Logo2 "FCC disclaimer" FCC_disclaimer 1020,50 r0 top
Logo3 "WEEE logo" WEEE_Minimum 730,280 r180 bottom
NT1 "Net-Tie" Net-Tie_10mil 4090,2620 r180 top net-tie
NT2 "Net-Tie" Net-Tie_10mil 2105,2110 r270 top net-tie
NT3 "Net-Tie" Net-Tie_10mil 1830,1875 r270 top net-tie
NT4 "Net-Tie" Net-Tie_10mil 4090,780 r180 top net-tie
NT5 "Net-Tie" Net-Tie_10mil 2105,1010 r270 top net-tie
Q1 "NVMFS6H848NLT1G" FP-NVMFS6H848NLT1G_DFN5-5x6-MFG 2739.18,2401.07 r0 top
Q2 "NVMFS6H848NLT1G" FP-NVMFS6H848NLT1G_DFN5-5x6-MFG 2969.18,2401.07 r0 top
Q4 "NVMFS6H801NLT1G" FP-NVMFS6H801NLT1G_DFN5-MFG 2970,2130 r0 top
Q5 "NVMFS6H801NLT1G" FP-NVMFS6H801NLT1G_DFN5-MFG 2737.54,2131.07 r0 top
Q7 "NVMFS6H848NLT1G" FP-NVMFS6H848NLT1G_DFN5-5x6-MFG 2739.18,1301.07 r0 top
Q8 "NVMFS6H848NLT1G" FP-NVMFS6H848NLT1G_DFN5-5x6-MFG 2970,1300 r0 top
Q9 "NVMFS6H801NLT1G" FP-NVMFS6H801NLT1G_DFN5-MFG 2967.54,1031.07 r0 top
Q10 "NVMFS6H801NLT1G" FP-NVMFS6H801NLT1G_DFN5-MFG 2737.54,1031.07 r0 top
R1 "CRCW25121R00JNEG" 2512 1560,3215 r270 bottom value=1.0
R2 "CRCW25121R00JNEG" 2512 1405,3215 r270 bottom value=1.0
R3 "RMCF0603ZT0R00" 0603L 2305,1160 r0 top value=0
R4 "RMCF0603ZT0R00" 0603L 2305,2250 r0 top value=0
R5 "DNP" FP-PML100HZPJV0L5_1225-MFG 3850,2380 r0 top value=500µ
R6 "CRCW0603150KFKEA" 0603L 1995,2305 r90 top value=150k
R7 "CRCW04020000Z0EDHP" 0402L 3825,2700 r180 top value=0
R8 "Y14830R00120F9R" FP-Y14830R00120F9R_2512-MFG 3850,2325 r0 top value=1.2m
R9 "CRCW04026K81FKED" 0402L 1945,2360 r270 top value=6.81k
R10 "DNP" 0402L 2265,2380 r0 top value=100k
R11 "DNP" 0603L 1880,2290 r180 top
R12 "CRCW040249R9FKED" 0402L 1890,2240 r180 top value=49.9
R13 "RMCF0402ZT0R00" "FP-RMCF0402ZT0R00_0402 (1005 metric)-0" 1855,2195 r180 top
R14 "DNP" 1210L 2955,1850 r0 top value=1.0
R15 "CRCW04020000Z0EDHP" 0402L 2085,2335 r270 top value=0
R16 "Used in BOM report" 0402L 1950,2215 r90 top
R17 "CRCW060349R9FKEA" 0603L 3500,3200 r0 top value=49.9
R18 "CRCW0402147KFKED" 0402L 1945,2075 r180 top value=147k
R19 "DNP" 0402L 2000,2015 r270 top value=100k
R20 "DNP" 0402L 2045,2335 r90 top value=0
R22 "DNP" 0402L 2155,1950 r270 top value=48.7k
R23 "RMCF0402FT100K" 0402L 2039,2015 r270 top value=100k
R24 "CRCW04023K01FKED" 0402L 1945,2035 r0 top value=3.01k
R25 "CRCW040254K9FKED" 0402L 1945,2115 r0 top value=54.9k
R26 "CRCW040219K1FKED" 0402L 2078,2014 r90 top value=19.1k
R29 "DNP" 0603L 1995,1205 r90 top value=100k
R30 "DNP" FP-PML100HZPJV0L5_1225-MFG 3850,1280 r0 top value=500µ
R31 "CRCW04020000Z0EDHP" 0402L 3825,1595 r0 top value=0
R32 "CRCW04020000Z0EDHP" 0402L 1890,2340 r0 top value=0
R33 "Y14830R00120F9R" FP-Y14830R00120F9R_2512-MFG 3850,1225 r0 top value=1.2m
R34 "DNP" 0402L 1945,1205 r270 top value=4.75k
R35 "RMCF0402FT100K" 0402L 2265,1290 r0 top value=100k
R36 "DNP" 0603L 1875,1190 r180 top
R37 "CRCW040249R9FKED" 0402L 1890,1140 r180 top value=49.9
R38 "RMCF0402ZT0R00" "FP-RMCF0402ZT0R00_0402 (1005 metric)-0" 1855,1095 r180 top
R39 "DNP" 1210L 2950,740 r0 top value=1.0
R40 "DNP" 0402L 2085,1205 r270 top value=0
R41 "Used in BOM report" 0402L 1950,1115 r90 top
R42 "DNP" 0603L 3500,200 r0 top value=49.9
R43 "CRCW04020000Z0EDHP" 0402L 2175,2380 r0 top value=0
R44 "CRCW0402147KFKED" 0402L 1940,975 r180 top value=147k
R45 "DNP" 0402L 2045,1205 r90 top value=0
R46 "DNP" 0402L 2000,915 r90 top value=100k
R48 "DNP" 0402L 1945,935 r0 top value=7.50k
R49 "CRCW04020000Z0EDHP" 0402L 1945,1955 r0 top value=0
R50 "DNP" 0402L 2040,915 r270 top value=100k
R51 "RMCF0402ZT0R00" "FP-RMCF0402ZT0R00_0402 (1005 metric)-0" 2155,850 r270 top
R52 "CRCW040290K9FKED" 0402L 1940,1015 r0 top value=90.9k
R53 "DNP" 0402L 2080,915 r90 top value=19.1k
R54 "RMCF0603ZT0R00" 0603L 2305,2195 r0 top value=0
R56 "RMCF0603ZT0R00" 0603L 2305,1105 r0 top value=0
R64 "DNP" FP-Y14830R00120F9R_2512-MFG 3850,2175 r0 top value=1.2m
R65 "DNP" FP-Y14830R00120F9R_2512-MFG 3850,1075 r0 top value=1.2m
R66 "DNP" FP-PML100HZPJV0L5_1225-MFG 3850,2120 r0 top value=500µ
R67 "DNP" FP-PML100HZPJV0L5_1225-MFG 3850,1020 r0 top value=500µ
SH-J1 "60900213421" Wurth_60900213421 7936,1789 r90 top
SH-J2 "60900213421" Wurth_60900213421 7706,1789 r90 top
T1 "Vout1" CB70-14-CY 4655,2700 r180 top
T2 "GND" CB70-14-CY 4650,1700 r180 top
T3 "Vout2" CB70-14-CY 4650,700 r180 top
TP1 "+Vin_Main" Testpoint_Keystone_Compact 150,2825 r180 bottom
TP2 "GND_In" Testpoint_Keystone_Compact 150,575 r180 bottom
TP3 "+VOUT1" Keystone5010 3700,3200 r0 top
TP4 "PG/SYNCOUT1" Keystone5012 2150,3200 r0 top
TP5 "SYNCIN1" Keystone5012 2550,3200 r0 top
TP6 "Bode1" Keystone5012 3300,3200 r0 top
TP7 "GND" Keystone5011 2900,200 r0 top
TP8 "GND" Keystone5011 2900,3200 r0 top
TP9 "+VOUT2" Keystone5010 3700,200 r0 top
TP10 "PG/SYNCOUT2" Keystone5012 2150,200 r0 top
TP11 "SYNCIN2" Keystone5012 2550,200 r0 top
TP12 "Bode2" Keystone5012 3300,200 r0 top
U2 "LM5148PSQRGYRQ1" RGY0020B-MFG 2115,2155 r90 top
U5 "LM5148PSQRGYRQ1" RGY0020B-MFG 2115,1055 r90 top

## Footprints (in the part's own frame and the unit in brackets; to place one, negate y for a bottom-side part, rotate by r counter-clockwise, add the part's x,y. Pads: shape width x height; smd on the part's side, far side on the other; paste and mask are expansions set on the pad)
0402L [mm] "0402 from SM-752 data"
  rect 0.6x0.5 smd: 1(-0.5,0) 2(0.5,0)
  body extent -0.55,-0.3 0.55,0.3, height 0.6
0603 [mm] "0603 from SM-752 data"
  rect 1x0.95 smd: 1(-0.8,0) 2(0.8,0)
  silkscreen extent -1.52,-0.69 1.52,0.69, body extent -0.87,-0.47 0.87,0.47, height 1
0603_HV [mil] "Ernesto recommended land pattern.  26 mil between pads."
  rect 30x30 smd: 1(-28,0) 2(28,0)
  silkscreen extent -52,-24 52,24, body extent -34,-19 34,19, height 39
0603L [mm] "0603 from SM-752 data"
  rect 0.8x0.85 smd: 1(-0.7,0) 2(0.7,0)
  silkscreen extent -0.07,-0.33 0.07,0.33, body extent -0.87,-0.47 0.87,0.47, height 1
0805_150 [mm] "0805 / 1.5 mm height"
  rect 1.15x1.45 smd: 1(-0.9,0) 2(0.9,0)
  silkscreen extent -0.1,-0.8 0.1,0.8, body extent -1.1,-0.72 1.1,0.72, height 1.5
0805L [mm] "0805 from SM-752 data"
  rect 1.1x1.4 smd: 1(-0.75,0) 2(0.75,0)
  body extent -1.1,-0.72 1.1,0.72, height 1.45
1206_180 [mm] "1206_180"
  rect 1.1x1.6 smd: 1(-1.7,0) 2(1.7,0)
  silkscreen extent -0.9,-1 0.9,1, body extent -1.75,-0.95 1.75,0.95, height 1.8
1210_220 [mm] "1210"
  rect 1.3x2.7 smd: 1(-1.45,0) 2(1.45,0)
  silkscreen extent -2.32,-1.57 2.32,1.57, body extent -1.7,-1.35 1.7,1.35, height 2.2
1210L [mm] "1210 from SM-752 data"
  rect 1.1x2.6 smd: 1(-1.35,0) 2(1.35,0)
  silkscreen extent -0.4,-1.2 0.4,1.2, body extent -1.7,-1.35 1.7,1.35, height 1.35
2512 [mm] "Chip Resistor, Body 6.3x3.2mm, IPC Medium Density"
  rect 1.3x3.4 smd: 1(-2.95,0) 2(2.95,0)
  silkscreen extent -1.9,-1.6 1.9,1.6, body extent -3.22,-1.67 3.22,1.67, height 0.71
7343-31 [mm] "Medium Density based on Kemet T495 dimensions"
  rect 2.55x2.45 smd: 1(-3.025,0) 2(3.025,0)
  silkscreen extent -4.56,-2.3 3.8,2.3, body extent -3.8,-2.3 3.8,2.3, height 3.1
CB70-14-CY [mil] "Terminal 90A Lug"
  rect 680x500 hole 254 copper offset -90,0 paste-250: 1(0,0)
  body extent -1300,-260 250,260, height 714
CE_Mark_5mm [mil] "Minimum text height for CE Mark"
  silkscreen extent -138,-98 138,98
Cinch_108-0902-001 [mil] "Banana Jack Insul Nylon Red, TH"
  rrect2% 320x220 smd: 1(185,0)
  body extent -666,-219 272,219, height 232
Cinch_108-0903-001 [mil] "Banana Jack Insul Nylon Black, TH"
  rrect2% 320x220 smd: 1(185,0)
  body extent -666,-219 272,219, height 232
FCC_disclaimer [mil]
Fiducial10-20 [mm]
  round 1 smd mask+0.5: 1(0,0)
  Top Layer keep-out circle w1.178: c0,0 r0.5
FP-EEE-TP1K391V_SMT_CAP_17MM0_17MM0-MFG [mm]
  round 4.009 smd paste+0 mask+0: 1(-5.97,-0.048)
  round 4.105 smd paste+0 mask+0: 2(6,0)
  Top Layer region: 2.9,-1.4 2.9,1.4 4.2,1.4 4.2,3.1 7.8,3.1 7.8,1.4 9.7,1.4 9.7,-1.4 7.8,-1.4 7.8,-3.1 4.2,-3.1 4.2,-1.4
  Top Layer region: -2.9,-1.4 -2.9,1.4 -4.2,1.4 -4.2,3.1 -7.8,3.1 -7.8,1.4 -9.7,1.4 -9.7,-1.4 -7.8,-1.4 -7.8,-3.1 -4.2,-3.1 -4.2,-1.4
  silkscreen extent -10.37,-8.6 8.6,8.6, body extent -8.85,-8.5 8.85,8.5, height 17.1
FP-GCJ32DC72A475KE01L_1210-MFG [mm]
  rrect9% 1.1x2.05 smd paste+0 mask+0: 1(-1.65,0) 2(1.65,0)
  silkscreen extent -1.8,-1.4 1.8,1.4, body extent -2.3,-1.5 2.3,1.5, height 0.25
FP-NVMFS6H801NLT1G_DFN5-MFG [mm]
  rrect13% 0.75x1 smd paste+0 mask+0: 1(-1.905,-2.748) 2(-0.635,-2.748) 3(0.635,-2.748) 4(1.905,-2.748)
  round 3.631 smd paste+0 mask+0: 5-6(-0.191,0.735)
  Top Layer region: -2.28,-1.282 -2.28,-0.857 -2.775,-0.857 -2.775,0.048 -2.28,0.048 -2.28,3.247 -1.53,3.247 -1.53,2.772 1.53,2.772 1.53,3.247 2.28,3.247 2.28,0.048 2.775,0.048 2.775,-0.857 2.28,-0.857 2.28,-1.282
  silkscreen extent -2.73,-3.05 2.73,3.05, body extent -2.88,-3.35 2.88,3.35, height 0.25
FP-NVMFS6H848NLT1G_DFN5-5x6-MFG [mm]
  rrect13% 0.75x1 smd paste+0 mask+0: 1(-1.905,-2.748) 2(-0.635,-2.748) 3(0.635,-2.748) 4(1.905,-2.748)
  round 3.631 smd paste+0 mask+0: 5-6(0.021,0.735)
  Top Layer region: -2.28,-1.282 -2.28,-0.857 -2.775,-0.857 -2.775,0.048 -2.28,0.048 -2.28,3.247 -1.53,3.247 -1.53,2.772 1.53,2.772 1.53,3.247 2.28,3.247 2.28,0.048 2.775,0.048 2.775,-0.857 2.28,-0.857 2.28,-1.282
  silkscreen extent -2.73,-3.05 2.73,3.05, body extent -2.88,-3.35 2.88,3.35, height 0.25
FP-PML100HZPJV0L5_1225-MFG [mm]
  rrect6% 1.7x6.4 smd paste+0 mask+0: 1(-1.25,0) 2(1.25,0)
  silkscreen extent -1.27,-3.63 1.27,3.63, body extent -2.2,-3.42 2.2,3.42, height 0.25
"FP-RMCF0402ZT0R00_0402 (1005 metric)-0" [mm]
  rrect20% 0.5x0.6 smd paste+0 mask+0: 1(-0.5,0) 2(0.5,0)
  body extent -0.85,-0.4 0.85,0.4, height 0.25
FP-SS10P4HM3_A/H_SMPC-MFG [mm]
  rrect8% 1.4x1.27 smd paste+0 mask+0: 1(1.04,-2.765) 2(-1.04,-2.765)
  rrect2% 4.8x4.72 smd paste+0 mask+0: 3(0,1.04)
  silkscreen extent -2.17,-3.08 2.17,-1.7, body extent -2.5,-3.5 2.5,3.5, height 0.25
FP-VCUD128T-2R5MS8_SMT_IND_13MM3_12MM8-MFG [mm]
  rrect3% 4x13.2 smd paste+0 mask+0: 1(-5.35,0) 2(5.35,0)
  silkscreen extent -2.98,-6.55 2.98,6.55, body extent -7.45,-6.7 7.45,6.7, height 0.25
FP-XGL1313-222MED_SMT_IND_13MM4_15MM0-MFG [mm]
  rrect3% 2.98x11.2 smd paste+0 mask+0: 1(-4.3,0) 2(4.3,0)
  silkscreen extent -7.87,-7.6 6.81,7.6, body extent -6.9,-7.7 6.9,7.7, height 0.25
FP-XGL6060-102MEC_SMT2_6MM51_6MM71-MFG [mm]
  rrect7% 1.43x5.5 smd paste+0 mask+0: 1(-2.02,0) 2(2.02,0)
  silkscreen extent -4.57,-3.45 3.35,3.45, body extent -3.25,-3.35 3.25,3.35, height 6.1
FP-Y14830R00120F9R_2512-MFG [mm]
  rrect6% 1.8x3.4 smd paste+0 mask+0: 1(-2.6,0) 2(2.6,0)
  silkscreen extent -0.25,-1.75 0.25,1.73, body extent -3.6,-1.85 3.6,1.85, height 0.25
Keystone5010 [mil] "Keystone Multipurpose loops"
  round 87 hole 63: 1(0,0)
  silkscreen extent -70,-70 70,70, body extent -63,-63 63,62, height 319
Keystone5011 [mil] "Keystone Multipurpose loops"
  round 87 hole 63: 1(0,0)
  silkscreen extent -70,-70 70,70, body extent -63,-63 63,62, height 319
Keystone5012 [mil] "Keystone Multipurpose loops"
  round 87 hole 63: 1(0,0)
  silkscreen extent -70,-70 70,70, body extent -63,-63 63,62, height 319
Keystone_1902C [mil] "Hex Standoff, 4-40 threaded, nylon"
  round 1 on Mech4: 0(0,0)
  body extent -145,-126 146,126, height 501
Keystone_5102 [mm] "Shorting Jumper, 5.375mm, 2 Position, SMT"
  rrect4% 2.475x3 smd: 1(-2.688,0) 2(2.688,0)
  body extent -3.42,-1.19 3.43,1.35, height 1
Label_650x200 [mil] "Thermal Transfer Label"
  round 1 on Mech13: 0(0,0)
  silkscreen extent -325,-100 325,100, body extent -325,-100 325,100, height 1
MuRata_PLT10H [mm] "SMD, 4-Leads, Body 12.9x6.6mm"
  rrect50% 1.5x2.6 smd: 1(-2.1,5.65) 2(2.1,5.65) 3(2.1,-5.65)
  rrect50% 1.5x2.61 smd: 4(-2.1,-5.65)
  silkscreen extent -3.61,-4.19 3.61,4.19, body extent -3.4,-6.7 3.4,6.7, height 9.4
Net-Tie_10mil [mil] "10mil net tie, no solder mask opening, no solder paste"
  rect 10x10 smd paste-5 mask-5: 1(-10,0) 2(10,0)
  Top Layer region: -6,5 6,5 6,-5 -6,-5
"NY PMS 440 0025 PH" [mm] "4-40 nylon screw and mounting hole"
  round 8 hole 3.2: 1(0,0)
  body extent -3.3,-3.3 3.3,3.3, height 2.69
POWERDI5 [mm] "Diodes Inc recommended land pattern, ap02001.pdf rev 60"
  rect 1.4x1.39 smd: 1(-1.991,0.92) 2(-1.991,-0.92)
  rect 4.86x3.36 smd: 3(1.991,0)
  silkscreen extent -1.7,-2.1 3.8,2.1, body extent -2.27,-2.03 4.33,2.03, height 1.17
RGY0020B-MFG [mm]
  rrect40% 0.25x0.6 smd paste+0 mask+0: 1(-0.75,2.15) 10(-0.75,-2.15) 11(0.75,-2.15) 20(0.75,2.15)
  rrect40% 0.6x0.25 smd paste+0 mask+0: 2(-1.65,1.75) 3(-1.65,1.25) 4(-1.65,0.75) 5(-1.65,0.25) 6(-1.65,-0.25) 7(-1.65,-0.75) 8(-1.65,-1.25) 9(-1.65,-1.75) 12(1.65,-1.75) 13(1.65,-1.25) 15(1.65,-0.25) 16(1.65,0.25) 17(1.65,0.75) 18(1.65,1.25) 19(1.65,1.75)
  rrect6% 1.7x2.7 smd paste-1000 mask+0: 21(0,0)
  silkscreen extent -1.8,-2.3 1.8,3.12, body extent -2.05,-2.55 2.05,2.55, height 0.25
SOD-123 [mm] "On Semi recommended land pattern"
  rect 0.915x1.22 smd: 1(-1.637,0) 2(1.637,0)
  silkscreen extent -2.74,-1.17 2.03,1.17, body extent -1.93,-0.9 1.93,0.9, height 1.35
SOD-323F [mm] "NXP recommended land pattern"
  rect 0.6x0.6 smd paste-0.05: 1(-1.1,0) 2(1.1,0)
  silkscreen extent -2.06,-0.86 1.53,0.86, body extent -1.35,-0.67 1.35,0.68, height 0.79
TDK_ACM12V [mm] "SMD, 4-Leads, Body 12x11mm, Pitch 5.2mm"
  rrect4% 3.2x2.7 smd: 1(-5.4,2.6) 2(-5.4,-2.6) 3(5.4,-2.6) 4(5.4,2.6)
  body extent -6,-5.5 6,5.5, height 5.55
Testpoint_Keystone_Compact [mil] "Compact SMT test point"
  rect 185x135 smd: 1(0,0)
  silkscreen extent -110,-80 110,80, body extent -75,-56 75,56, height 91
TSW-102-07-G-S [mm] "Samtec 100mil, 1x2, 230 mil above insulator"
  rrect50% 1.65x1.65 hole 1.016: 1(-1.27,0)
  round 1.65 hole 1.016: 2(1.27,0)
  silkscreen extent -3.17,-1.27 2.54,1.27, body extent -2.54,-1.27 2.54,1.27, height 8.38
WEEE_Minimum [mil] "WEEElie bin"
  silkscreen extent -95,-172 99,104
Wurth_60900213421 [mil] "Shunt, 2.54mm, Black"
  round 1 on Mech3: 0(0,0)
  body extent -98,-48 98,48, height 338

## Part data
C1: library part CMP-0048820-1, "Cap Aluminum Lytic 390uF 80V 20% (16 X 16.5mm) SMD 0.1 Ohm 1900mA 3000h 125°C Automotive T/R", Digikey Part Number=P123481CT-ND, Leakage Current=312uA, Manufacturer=Panasonic, Mouser Part Number=667-EEE-TP1K391V, Operating Temperature Range="-55°C to +125°C", Tolerance_%=20%, ValueDisplayed=390uF
C2 C3 C7 C8 C9: library part CMP-0084773-1, "CAP, CERM, 0.01 µF, 100 V,+/- 10%, X7R, AEC-Q200 Grade 1, 0603", Cap_Case=0603, Manufacturer=MuRata, TempCo=X7R, Tolerance_%=10%, Value2=100V, ValueDisplayed=0.01µF
C4: library part CMP-0008790-2, "CAP, CERM, 2.2 uF, 100 V, +/- 10%, X7S, AEC-Q200 Grade 1, 1206", Cap_Case=1206_180, Manufacturer=TDK, Supplier Part Number 1=445-6994-1-ND, TempCo=X7S, Tolerance_%=10%, Value1="0.005718 ohm", Value2=100V, ValueDisplayed=2.2uF
C5: library part CMP-0009134-2, "CAP, CERM, 4.7 uF, 100 V, +/- 10%, X7S, 1210", Cap_Case=1210_220, Manufacturer=TDK, Supplier Part Number 1=445-6042-1-ND, TempCo=X7S, Tolerance_%=10%, Value1="0.004236 ohm", Value2=100V, ValueDisplayed=4.7uF
C6: library part CMP-0009150-2, "CAP, CERM, 4.7 uF, 100 V, +/- 10%, X7S, AEC-Q200 Grade 1, 1210", Cap_Case=1210_220, Manufacturer=TDK, Supplier Part Number 1=445-7005-1-ND, TempCo=X7S, Tolerance_%=10%, Value1="0.004236 ohm", Value2=100V, ValueDisplayed=4.7uF
C10 C11: library part CMP-0861070-1, "CAP, CERM, 1 µF, 100 V,+/- 10%, X7R, AEC-Q200 Grade 1, 0805", Cap_Case=0805, Manufacturer=AVX, TempCo=X7R, Tolerance_%=10%, Value2=100V, ValueDisplayed=1µF
C12 C13 C14 C15 C16 C54 C55 C56 C57 C58 C100 C101: library part CMP-0093675-1, "4.7uF ±10% 100V Ceramic Capacitor X7S 1210 (3225 Metric)", Manufacturer=Murata, Operating Temperature Range="-55°C to +125°C", TempCo=22%, Temperature Characteristic=X7S, Tolerance_%=10%, ValueDisplayed=4.7uF
C17 C18 C19 C20 C59 C60 C61 C62: library part CMP-0064935-4, "CAP, CERM, 0.1 uF, 100 V,+/- 10%, X7R, AEC-Q200 Grade 1, 0603", Cap_Case=0603, Manufacturer=MuRata, Supplier Part Number 1=490-13420-1-ND, TempCo=X7R, Tolerance_%=10%, Value1=Unknown, Value2=100V, ValueDisplayed=0.1uF
C21 C22 C23 C24 C29 C63 C64 C65 C66 C67 C102 C103: library part CMP-0093675-1, "4.7uF ±10% 100V Ceramic Capacitor X7S 1210 (3225 Metric)", Manufacturer=Murata, Operating Temperature Range="-55°C to +125°C", Part Number=GCJ32DC72A475KE01L, TempCo=22%, Temperature Characteristic=X7S, Tolerance_%=10%, ValueDisplayed=4.7uF
C25 C26 C27 C28 C68 C69 C70 C71: library part CMP-0064935-4, "CAP, CERM, 0.1 uF, 100 V,+/- 10%, X7R, AEC-Q200 Grade 1, 0603", Cap_Case=0603, Manufacturer=MuRata, PartNumber=GCJ188R72A104KA01D, Supplier Part Number 1=490-13420-1-ND, TempCo=X7R, Tolerance_%=10%, Value1=Unknown, Value2=100V, ValueDisplayed=0.1uF
C30 C72: library part Capacitor, "CAP, CERM, xxxF, xxV, [TempCo], xx%, [PackageReference]", Alternate Manufacturer=-, Manufacturer="Kyocera AVX", Value1=100V
C32 C74: library part Capacitor, "CAP, CERM, 0.22uF, 35V, X7R, 10%, 0402", Alternate Manufacturer=-, Manufacturer=TDK, Value1=35V
C33 C48 C75 C90: library part CMP-0079150-1, "CAP, CERM, 0.1 µF, 10 V,+/- 10%, X7R, AEC-Q200 Grade 1, 0402", Cap_Case=0402, Manufacturer=Kemet, Supplier Part Number 1=399-15984-1-ND, TempCo=X7R, Tolerance_%=10%, Value2=10V, ValueDisplayed=0.1µF
C34 C76: library part CMP-0007498-4, "CAP, CERM, 4.7 uF, 10 V, +/- 20%, X7R, 0603", Cap_Case=0603, Manufacturer=MuRata, TempCo=X7R, Tolerance_%=20%, Value1=Unknown, Value2=10V, ValueDisplayed=4.7uF
C35 C77: library part Capacitor, "CAP, CERM, 330F, 100V, C0G, 5%, 0603", Alternate Manufacturer=-, Manufacturer=Murata, PartNumber=GCM1885C2A331JA16D, Value1=100V
C36 C37 C78 C79: library part CMP-0012661-3, "CAP, Tantalum Polymer, 220 uF, 10 V, +/- 20%, 0.025 ohm, AEC-Q200 Grade 1, 7343-31 SMD", Cap_Case=7.3x4.3x3.1mm, Manufacturer=Kemet, PartNumber=T598D227M010ATE025, Supplier Part Number 1=399-12102-1-ND, Tolerance_%=20%, Value1="0.025 ohm", Value2=10V, ValueDisplayed=220uF
C38 C39 C40 C41 C43 C44 C45 C46 C80 C81 C82 C83 C85 C86 C87 C88: library part Capacitor, "CAP, CERM, 100uF, 6.3V, X7S, 20%, 1210", Alternate Manufacturer=-, Manufacturer=Murata, Value1=6.3V
C42 C84 C89: library part CMP-0006861-4, "CAP, CERM, 0.1 uF, 50 V, +/- 10%, X7R, 0603", Cap_Case=0603, Manufacturer=Kemet, Supplier Part Number 1=399-5089-1-ND, TempCo=X7R, Tolerance_%=10%, Value1=Unknown, Value2=50V, ValueDisplayed=0.1uF
C47: library part CMP-0006861-4, "CAP, CERM, 0.1 uF, 50 V, +/- 10%, X7R, 0603", Cap_Case=0603, Manufacturer=Kemet, PartNumber=C0603C104K5RACTU, Supplier Part Number 1=399-5089-1-ND, TempCo=X7R, Tolerance_%=10%, Value1=Unknown, Value2=50V, ValueDisplayed=0.1uF
C49 C91: library part CMP-0006306-2, "CAP, CERM, 0.033 uF, 25 V, +/- 10%, X7R, AEC-Q200 Grade 1, 0402", Cap_Case=0402, Manufacturer=TDK, Supplier Part Number 1=445-12247-1-ND, TempCo=X7R, Tolerance_%=10%, Value1=Unknown, Value2=25V, ValueDisplayed=0.033uF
